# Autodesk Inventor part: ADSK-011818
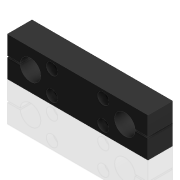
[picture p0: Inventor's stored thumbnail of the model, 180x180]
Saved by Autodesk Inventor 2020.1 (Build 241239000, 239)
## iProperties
Created: 1999-12
Part Number: ADSK-011818
Document SubType Name: Modeling
Designer: glanglot
Material: Générique
Density: 1 g/cm^3
Appearance: Rubber-Black
Mass: 104.03 g
Surface Area: 237.17 cm^2
Volume: 104.03 cm^3
Control State: 0
Master: False
Checked Out: False
Shininess: 0.0
Length Units: 11269
Angle Units: 11279
Time Units: 11290
Mass Units: 11283
Length Display Precision: 3
Angle Display Precision: 2
Compacted: True
Dimensions: 137x38x24 mm
Mass: 0,104 kg
Density: 0.0
Volumn: 0.0
Area: 0.0
PropertySet Name: Model Information
Author: glanglot
Revision Number: -
Title: ADSK-011818
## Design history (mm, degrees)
node "Extrusion1" dims "d2" = 24, "d3" = 0
  sketch "Sketch1"
    geometry: L1 (-68.5, 19)-(68.5, 19); L2 (68.5, 19)-(68.5, -19); L3 (68.5, -19)-(-68.5, -19); L4 (-68.5, -19)-(-68.5, 19); 3 further points
    constraints: 8 end point, 2 midpoint, 2 parallel, 1 horizontal, 1 horizontal alignment, 1 perpendicular, 1 vertical alignment
    dimensions: "d0" = 38 distance of L3.end L1.start; "d1" = 137 distance of L2.end L3.end
node "Hole1" dims "d8" = 6.6, "d9" = 11, "d10" = 6.8, "d11" = 60 deg, "d12" = 19.05, "d13" = 118 deg, "d33" = 12.7
  sketch "Sketch2"
    geometry: L1 (-68.5, 19)-(68.5, 19) reference; L2 (-68.5, -19)-(-68.5, 19) reference; L3 (-25, 11.25)-(25, 11.25); L4 (25, 11.25)-(25, -11.25); L5 (25, -11.25)-(-25, -11.25); L6 (-25, -11.25)-(-25, 11.25); 6 further points
    constraints: 8 end point, 4 midpoint, 3 horizontal alignment, 3 vertical alignment, 2 parallel, 1 horizontal, 1 perpendicular
    dimensions: "d31" = 50 distance of L3.start L3.end; "d32" = 22.5 distance of L3.end L4.end
node "Hole2" dims "d17" = 20, "d18" = 11.1125, "d19" = 6.985, "d20" = 60 deg, "d21" = 19.05, "d22" = 118 deg, "d35" = 6
  sketch "Sketch3"
    geometry: L1 (-68.5, 19)-(68.5, 19) reference; L2 (-68.5, -19)-(-68.5, 19) reference; L3 (-46, 0)-(46, 0); 3 further points
    constraints: 3 midpoint, 2 end point, 2 horizontal alignment, 1 horizontal, 1 vertical alignment
    dimensions: "d34" = 92 distance of L3.start L3.end
node "Extrusion2" dims "d25" = 24.13, "d26" = 0
  sketch "Sketch4"
    geometry: L1 (-24.13, 19)-(0, 19); L2 (-24.13, 19.75)-(-0.13, 19.75); L3 (-24.13, 18.25)-(-0.13, 18.25); L4 (-24.13, 19.75)-(-24.13, 18.25) reference; L5 (-0.13, 18.25)-(-0.13, 19.75); L6 (0, 0)-(-24, 0) reference; L7 (0, 0)-(0, 38) reference; 1 further point
    constraints: 10 end point, 1 coincident, 1 midpoint, 1 parallel, 1 perpendicular, 1 vertical
    dimensions: "d23" = 0.75 distance between parallel lines of L2 L1; "d24" = 0.75 distance between parallel lines of L3 L1 (= d23); "d29" = 24 distance of L3.start L3.end (= d2)
mirror "Spiegeln1"
node "Solide1"
node "Corps solides"
node "Corps surfaciques"
